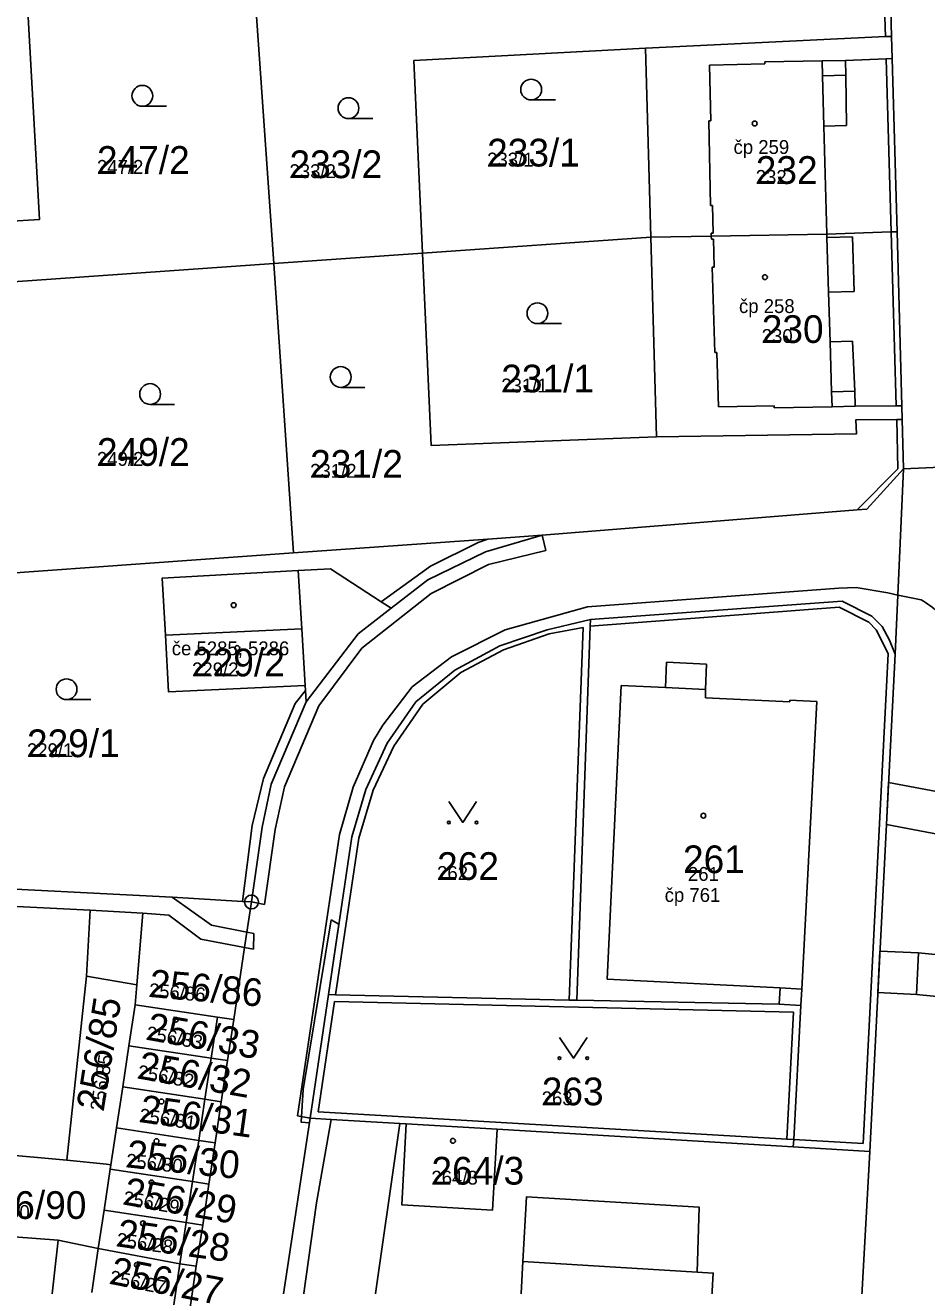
# Model space of a CAD drawing. Extents: x -763628 to -761565, y -976033 to -973833.
# Drawn here: x -762377.8 to -762312.8, y -974602.2 to -974511.2 of the extents above; entities that cross this region are included whole.
import ezdxf

# ---------------------------------------------------------------- set-up
doc = ezdxf.new("R2010")
doc.units = 0
for name, color, linetype in [('KN_cisla parcel 1000', 7, 'Continuous'), ('KN_cisla parcel 500', 7, 'Continuous'), ('KN_cisla popisna 500', 7, 'Continuous'), ('KN_hranice parcel', 7, 'Continuous'), ('KN_vecna bremena', 7, 'Continuous'), ('KN_vnitrni kresba parcel', 7, 'Continuous'), ('KN_znacky bodu BP', 7, 'Continuous'), ('KN_znacky budov', 7, 'Continuous'), ('KN_znacky kultur', 7, 'Continuous')]:
    doc.layers.add(name, color=color, linetype=linetype)

msp = doc.modelspace()

# ---------------------------------------------------------------- linework, layer by layer
at = {"layer": 'KN_hranice parcel'}
for p, q in [((-762315.48, -974505.83), (-762315.31, -974512)), ((-762361.25, -974508.46), (-762359.88, -974528.4)), ((-762333.06, -974512.85), (-762332.67, -974526.49)), ((-762332.67, -974526.49), (-762349.14, -974527.65)), ((-762332.67, -974526.49), (-762332.26, -974540.9)), ((-762349.14, -974527.65), (-762359.88, -974528.4)), ((-762378.68, -974529.71), (-762359.88, -974528.4)), ((-762359.88, -974528.4), (-762358.44, -974549.26)), ((-762314.53, -974539.65), (-762314.44, -974543.2)), ((-762358.44, -974549.26), (-762383.59, -974551.08)), ((-762316.87, -974592.46), (-762315.05, -974556.59)), ((-762373.12, -974575.06), (-762402.53, -974573.6)), ((-762369.33, -974575.27), (-762373.12, -974575.06)), ((-762362.76, -974582.94), (-762361.98, -974577.75)), ((-762355.92, -974581.14), (-762357.24, -974590.06)), ((-762369.88, -974581.87), (-762370.32, -974584.83)), ((-762363.21, -974585.91), (-762362.76, -974582.94)), ((-762370.32, -974584.83), (-762370.77, -974587.8)), ((-762363.66, -974588.87), (-762363.21, -974585.91)), ((-762370.77, -974587.8), (-762371.22, -974590.76)), ((-762364.1, -974591.84), (-762363.66, -974588.87)), ((-762350.32, -974590.47), (-762343.75, -974590.86)), ((-762371.22, -974590.76), (-762371.62, -974593.42)), ((-762343.75, -974590.86), (-762322.39, -974592.13)), ((-762364.55, -974594.81), (-762364.1, -974591.84)), ((-762322.39, -974592.13), (-762316.87, -974592.46)), ((-762382.37, -974592.4), (-762374.81, -974593.08)), ((-762371.67, -974593.73), (-762372.12, -974596.69)), ((-762371.62, -974593.42), (-762371.67, -974593.73)), ((-762365, -974597.77), (-762364.55, -974594.81)), ((-762372.12, -974596.69), (-762372.54, -974599.47)), ((-762365.46, -974600.74), (-762365, -974597.77)), ((-762377.48, -974617.38), (-762375.43, -974598.87)), ((-762372.54, -974599.47), (-762375.43, -974598.87)), ((-762372.54, -974599.47), (-762373.01, -974602.63)), ((-762365.9, -974603.71), (-762365.46, -974600.74))]:
    msp.add_line(p, q, dxfattribs=at)
for points in [[(-762385.82, -974525.76), (-762376.78, -974525.22), (-762377.64, -974509.75)], [(-762315.31, -974512), (-762315.74, -974512.02), (-762333.06, -974512.85)], [(-762314.9, -974526.1), (-762315.26, -974513.59), (-762315.31, -974512)], [(-762333.06, -974512.85), (-762349.76, -974513.75), (-762349.14, -974527.65)], [(-762314.9, -974526.1), (-762315.33, -974526.11), (-762319.97, -974526.27), (-762328.31, -974526.41), (-762332.67, -974526.49)], [(-762314.53, -974539.65), (-762314.56, -974538.66), (-762314.9, -974526.1)], [(-762349.14, -974527.65), (-762348.52, -974541.52), (-762332.26, -974540.9)], [(-762332.26, -974540.9), (-762317.84, -974540.69), (-762317.88, -974539.67), (-762314.93, -974539.65), (-762314.53, -974539.65)], [(-762314.44, -974543.2), (-762317.09, -974546.11), (-762317.78, -974546.17), (-762340.52, -974547.99)], [(-762314.44, -974543.2), (-762314.86, -974552.31), (-762315.05, -974556.59)], [(-762340.52, -974547.99), (-762344.42, -974548.27), (-762358.44, -974549.26)], [(-762351.4, -974553.27), (-762348.76, -974551.22), (-762344.6, -974549.19), (-762340.52, -974547.99)], [(-762357.54, -974560.01), (-762357.59, -974559.2), (-762357.61, -974558.85), (-762367.46, -974559.3), (-762367.69, -974555.2), (-762367.92, -974551.09), (-762358.11, -974550.55), (-762355.78, -974550.42), (-762352.12, -974552.8), (-762351.4, -974553.27)], [(-762315.05, -974556.59), (-762315.46, -974555.58), (-762315.98, -974554.59), (-762316.72, -974553.83), (-762318.87, -974552.75), (-762337.03, -974554.08)], [(-762357.54, -974560.01), (-762353.78, -974555.1), (-762351.4, -974553.27)], [(-762337.03, -974554.08), (-762337.53, -974554.2), (-762340.15, -974554.82), (-762343.57, -974555.97), (-762346.81, -974557.74), (-762349.62, -974560.02), (-762351.7, -974562.99), (-762353.24, -974566.35), (-762354.23, -974569.77), (-762355.92, -974581.14)], [(-762337.03, -974554.08), (-762337.05, -974554.57), (-762338.01, -974581.55)], [(-762361.48, -974574.46), (-762360.72, -974569.05), (-762360.06, -974565.95), (-762357.54, -974560.01)], [(-762383.26, -974573.3), (-762367.2, -974574.11), (-762362.14, -974574.42), (-762361.48, -974574.46)], [(-762374.81, -974593.08), (-762373.39, -974579.82), (-762373.12, -974575.06)], [(-762361.98, -974577.75), (-762361.81, -974576.64), (-762361.48, -974574.46)], [(-762369.88, -974581.87), (-762369.76, -974580.43), (-762369.33, -974575.27)], [(-762361.98, -974577.75), (-762365.13, -974577.14), (-762367.45, -974575.41), (-762369.33, -974575.27)], [(-762355.92, -974581.14), (-762355.41, -974581.15), (-762338.55, -974581.54), (-762338.01, -974581.55)], [(-762362.76, -974582.94), (-762363.94, -974582.76), (-762369.88, -974581.87)], [(-762338.01, -974581.55), (-762323.4, -974581.83), (-762321.84, -974581.92), (-762322.36, -974591.6), (-762322.39, -974592.13)], [(-762363.21, -974585.91), (-762364.39, -974585.73), (-762370.32, -974584.83)], [(-762363.66, -974588.87), (-762364.84, -974588.69), (-762370.77, -974587.8)], [(-762357.24, -974590.06), (-762362.84, -974626.97), (-762363.63, -974631.1), (-762365.36, -974638.07), (-762367.56, -974644.53)], [(-762357.24, -974590.06), (-762355.74, -974590.15), (-762350.77, -974590.44), (-762350.32, -974590.47)], [(-762343.75, -974590.86), (-762344.1, -974596.7), (-762350.64, -974596.31), (-762350.32, -974590.47)], [(-762364.1, -974591.84), (-762365.29, -974591.66), (-762371.22, -974590.76)], [(-762375.43, -974598.87), (-762383.08, -974598.28), (-762382.37, -974592.4)], [(-762374.81, -974593.08), (-762371.94, -974593.39), (-762371.62, -974593.42)], [(-762319.64, -974642.39), (-762319.28, -974635.8), (-762316.87, -974592.46)], [(-762364.55, -974594.81), (-762365.74, -974594.63), (-762371.67, -974593.73)], [(-762324.2, -974627.44), (-762338.71, -974626.51), (-762341.63, -974626.32), (-762342.11, -974634.68), (-762342.19, -974635.75), (-762342.28, -974636.95), (-762346.13, -974636.78), (-762345.95, -974635.59), (-762345.4, -974624.52), (-762351.39, -974623.22), (-762351.21, -974622.61), (-762350.73, -974620.91), (-762345.24, -974622.18), (-762343.05, -974622.69), (-762341.91, -974600.41), (-762341.64, -974595.74), (-762329.18, -974596.49), (-762329.32, -974601.17), (-762328.16, -974601.24), (-762328.39, -974605.06), (-762328.16, -974605.07), (-762328.37, -974608.45), (-762323.2, -974608.77), (-762324.2, -974627.44)], [(-762365, -974597.77), (-762366.19, -974597.59), (-762372.12, -974596.69)], [(-762365.46, -974600.74), (-762366.64, -974600.56), (-762372.54, -974599.47)]]:
    msp.add_lwpolyline(points, dxfattribs=at)
at = {"layer": 'KN_vecna bremena'}
for points in [[(-762315.67, -974568.86), (-762311.86, -974569.58), (-762311.3, -974566.64), (-762315.52, -974565.83)], [(-762355.74, -974575.74), (-762357.74, -974587.99), (-762357.89, -974590.36), (-762357.29, -974590.4), (-762357.24, -974590.06), (-762355.92, -974581.14), (-762355.17, -974576.07)], [(-762316.14, -974578), (-762316.29, -974581), (-762313.5, -974581.13), (-762305.88, -974581.89), (-762305.61, -974578.91), (-762313.36, -974578.13)], [(-762316.29, -974581), (-762313.5, -974581.13), (-762313.36, -974578.13), (-762316.14, -974578)]]:
    msp.add_lwpolyline(points, close=True, dxfattribs=at)
at = {"layer": 'KN_vnitrni kresba parcel'}
for p, q in [((-762315.74, -974512.02), (-762315.92, -974505.86)), ((-762328.44, -974514.07), (-762324.44, -974513.99)), ((-762328.34, -974518.1), (-762328.44, -974514.07)), ((-762324.44, -974513.84), (-762320.31, -974513.76)), ((-762324.44, -974513.99), (-762324.44, -974513.84)), ((-762320.31, -974513.76), (-762318.62, -974513.73)), ((-762320.28, -974514.85), (-762320.31, -974513.76)), ((-762318.62, -974513.73), (-762315.69, -974513.61)), ((-762318.62, -974513.73), (-762318.6, -974514.81)), ((-762315.69, -974513.61), (-762315.26, -974513.59)), ((-762315.33, -974526.11), (-762315.69, -974513.61)), ((-762320.28, -974514.85), (-762318.6, -974514.81)), ((-762320.18, -974518.47), (-762320.28, -974514.85)), ((-762318.6, -974514.81), (-762318.55, -974518.42)), ((-762328.36, -974524.21), (-762328.49, -974518.1)), ((-762328.49, -974518.1), (-762328.34, -974518.1)), ((-762318.55, -974518.42), (-762320.18, -974518.47)), ((-762320.18, -974518.47), (-762319.97, -974526.27)), ((-762328.21, -974524.21), (-762328.36, -974524.21)), ((-762328.16, -974526.21), (-762328.21, -974524.21)), ((-762328.31, -974526.41), (-762328.31, -974526.21)), ((-762328.31, -974526.21), (-762328.16, -974526.21)), ((-762328.3, -974526.63), (-762328.31, -974526.41)), ((-762328.15, -974526.63), (-762328.3, -974526.63)), ((-762328.09, -974528.65), (-762328.15, -974526.63)), ((-762319.97, -974526.27), (-762319.96, -974526.52)), ((-762318.12, -974526.46), (-762319.96, -974526.52)), ((-762319.96, -974526.52), (-762319.84, -974530.46)), ((-762317.99, -974530.4), (-762318.12, -974526.46)), ((-762314.96, -974538.66), (-762315.33, -974526.11)), ((-762328.24, -974528.66), (-762328.09, -974528.65)), ((-762328.06, -974534.81), (-762328.24, -974528.66)), ((-762319.84, -974530.46), (-762317.99, -974530.4)), ((-762319.84, -974530.46), (-762319.74, -974534.05)), ((-762319.74, -974534.05), (-762318.11, -974534)), ((-762319.63, -974537.66), (-762319.74, -974534.05)), ((-762318.11, -974534), (-762317.96, -974537.61)), ((-762327.91, -974534.8), (-762328.06, -974534.81)), ((-762327.79, -974538.73), (-762327.91, -974534.8)), ((-762317.96, -974537.61), (-762319.63, -974537.66)), ((-762319.63, -974537.66), (-762319.59, -974538.73)), ((-762317.96, -974537.61), (-762317.92, -974538.68)), ((-762323.77, -974538.66), (-762327.79, -974538.73)), ((-762323.77, -974538.81), (-762323.77, -974538.66)), ((-762317.92, -974538.68), (-762319.59, -974538.73)), ((-762314.96, -974538.66), (-762317.92, -974538.68)), ((-762314.56, -974538.66), (-762314.96, -974538.66)), ((-762319.59, -974538.73), (-762323.77, -974538.81)), ((-762314.93, -974539.65), (-762314.84, -974543.2)), ((-762317.78, -974546.17), (-762314.84, -974543.2)), ((-762309.47, -974542.99), (-762314.44, -974543.2)), ((-762348.57, -974550.24), (-762345.13, -974548.53)), ((-762345.13, -974548.53), (-762344.42, -974548.27)), ((-762340.25, -974549.09), (-762340.52, -974547.99)), ((-762344.37, -974550.1), (-762340.25, -974549.09)), ((-762352.12, -974552.8), (-762348.57, -974550.24)), ((-762348.52, -974552.21), (-762344.37, -974550.1)), ((-762357.85, -974554.74), (-762358.11, -974550.55)), ((-762353.51, -974556.15), (-762348.52, -974552.21)), ((-762337.25, -974553.17), (-762319.1, -974551.82)), ((-762319.1, -974551.82), (-762317.86, -974551.77)), ((-762317.86, -974551.77), (-762315.58, -974552.16)), ((-762315.58, -974552.16), (-762314.86, -974552.31)), ((-762314.86, -974552.31), (-762313.17, -974552.67)), ((-762343.19, -974554.82), (-762337.25, -974553.17)), ((-762319.09, -974553.19), (-762337.05, -974554.57)), ((-762316.94, -974554.28), (-762319.09, -974553.19)), ((-762367.69, -974555.2), (-762357.85, -974554.74)), ((-762357.61, -974558.85), (-762357.85, -974554.74)), ((-762347.05, -974556.78), (-762343.19, -974554.82)), ((-762340.01, -974555.1), (-762337.55, -974554.66)), ((-762337.55, -974554.66), (-762338.55, -974581.54)), ((-762316.42, -974554.82), (-762316.94, -974554.28)), ((-762315.9, -974555.81), (-762316.42, -974554.82)), ((-762343.31, -974556.27), (-762340.01, -974555.1)), ((-762315.55, -974556.56), (-762315.9, -974555.81)), ((-762356.62, -974560.31), (-762353.51, -974556.15)), ((-762349.89, -974558.93), (-762347.05, -974556.78)), ((-762346.38, -974557.91), (-762343.31, -974556.27)), ((-762317.34, -974591.89), (-762315.55, -974556.56)), ((-762331.62, -974558.99), (-762331.53, -974557.16)), ((-762331.53, -974557.16), (-762328.65, -974557.3)), ((-762328.65, -974557.3), (-762328.73, -974559.13)), ((-762349.13, -974560.18), (-762346.38, -974557.91)), ((-762358.34, -974560.13), (-762357.59, -974559.2)), ((-762352.01, -974561.7), (-762349.89, -974558.93)), ((-762335.82, -974580.02), (-762334.82, -974558.84)), ((-762334.82, -974558.84), (-762331.62, -974558.99)), ((-762328.73, -974559.13), (-762331.62, -974558.99)), ((-762328.73, -974559.13), (-762328.72, -974559.72)), ((-762360.61, -974565.56), (-762358.34, -974560.13)), ((-762359.1, -974566.14), (-762356.62, -974560.31)), ((-762351.21, -974563.21), (-762349.13, -974560.18)), ((-762328.72, -974559.72), (-762322.65, -974560.03)), ((-762322.65, -974560.03), (-762322.65, -974559.89)), ((-762322.65, -974559.89), (-762320.69, -974559.99)), ((-762320.69, -974559.99), (-762321.78, -974580.74)), ((-762352.67, -974562.8), (-762352.01, -974561.7)), ((-762354.15, -974566.17), (-762352.67, -974562.8)), ((-762352.71, -974566.39), (-762351.21, -974563.21)), ((-762361.42, -974568.93), (-762360.61, -974565.56)), ((-762359.78, -974569.23), (-762359.1, -974566.14)), ((-762355.12, -974569.6), (-762354.15, -974566.17)), ((-762353.74, -974569.85), (-762352.71, -974566.39)), ((-762362.14, -974574.42), (-762361.42, -974568.93)), ((-762360.55, -974574.65), (-762359.78, -974569.23)), ((-762358.17, -974589.88), (-762355.12, -974569.6)), ((-762355.41, -974581.15), (-762353.74, -974569.85)), ((-762367.2, -974574.11), (-762364.36, -974576.14)), ((-762361.48, -974574.46), (-762360.55, -974574.65)), ((-762364.36, -974576.14), (-762361.81, -974576.64)), ((-762361.81, -974576.64), (-762361.31, -974576.74)), ((-762361.31, -974576.74), (-762361.33, -974577.87)), ((-762361.33, -974577.87), (-762361.98, -974577.75)), ((-762373.39, -974579.82), (-762369.76, -974580.43)), ((-762323.34, -974580.66), (-762335.82, -974580.02)), ((-762323.4, -974581.83), (-762323.34, -974580.66)), ((-762323.34, -974580.66), (-762321.78, -974580.74)), ((-762321.78, -974580.74), (-762321.84, -974581.92)), ((-762355.48, -974581.63), (-762356.66, -974589.6)), ((-762322.37, -974582.41), (-762355.48, -974581.63)), ((-762363.94, -974582.76), (-762364.39, -974585.73)), ((-762322.86, -974591.57), (-762322.37, -974582.41)), ((-762364.39, -974585.73), (-762364.84, -974588.69)), ((-762364.84, -974588.69), (-762365.29, -974591.66)), ((-762356.66, -974589.6), (-762322.86, -974591.57)), ((-762357.24, -974590.06), (-762358.17, -974589.88)), ((-762355.74, -974590.15), (-762356.78, -974596.18)), ((-762353.83, -974611.61), (-762350.77, -974590.44)), ((-762365.29, -974591.66), (-762365.74, -974594.63)), ((-762322.86, -974591.57), (-762322.36, -974591.6)), ((-762322.36, -974591.6), (-762317.34, -974591.89)), ((-762365.74, -974594.63), (-762366.19, -974597.59)), ((-762356.78, -974596.18), (-762360.24, -974620.63)), ((-762366.19, -974597.59), (-762366.64, -974600.56)), ((-762341.91, -974600.41), (-762329.32, -974601.17)), ((-762366.64, -974600.56), (-762367.08, -974603.53))]:
    msp.add_line(p, q, dxfattribs=at)
msp.add_lwpolyline([(-762313.17, -974552.67), (-762313.004, -974552.761), (-762312.842, -974552.859), (-762312.684, -974552.962), (-762312.531, -974553.072), (-762312.381, -974553.187), (-762312.236, -974553.309), (-762312.096, -974553.435), (-762311.961, -974553.567), (-762311.831, -974553.705), (-762311.706, -974553.847), (-762311.587, -974553.994), (-762311.474, -974554.145), (-762311.367, -974554.301), (-762311.266, -974554.46), (-762311.171, -974554.624), (-762311.082, -974554.791), (-762311, -974554.961), (-762310.925, -974555.134), (-762310.856, -974555.31), (-762310.795, -974555.489), (-762310.74, -974555.67)], dxfattribs=at)
at = {"layer": 'KN_znacky bodu BP'}
for radius in [0.5, 0.0303]:
    msp.add_circle((-762361.48, -974574.46), radius, dxfattribs=at)
at = {"layer": 'KN_znacky budov'}
for centre in [(-762325.177, -974518.289), (-762324.437, -974529.379), (-762362.767, -974553.039), (-762362.507, -974556.139), (-762328.877, -974568.229), (-762366.947, -974582.959), (-762367.507, -974585.829), (-762367.977, -974588.859), (-762368.337, -974591.719), (-762346.947, -974591.699), (-762368.697, -974594.699), (-762369.307, -974597.649), (-762369.747, -974600.649)]:
    msp.add_circle(centre, 0.175, dxfattribs=at)
at = {"layer": 'KN_znacky kultur'}
for p, q in [((-762341.303, -974516.59), (-762339.553, -974516.59)), ((-762369.353, -974517.04), (-762367.603, -974517.04)), ((-762354.483, -974517.93), (-762352.733, -974517.93)), ((-762340.853, -974532.73), (-762339.103, -974532.73)), ((-762355.043, -974537.33), (-762353.293, -974537.33)), ((-762368.793, -974538.56), (-762367.043, -974538.56)), ((-762374.823, -974559.86), (-762373.073, -974559.86))]:
    msp.add_line(p, q, dxfattribs=at)
for points in [[(-762347.24, -974567.219), (-762346.24, -974568.72), (-762345.24, -974567.219)], [(-762339.26, -974584.229), (-762338.26, -974585.73), (-762337.26, -974584.229)]]:
    msp.add_lwpolyline(points, dxfattribs=at)
for centre, radius in [((-762369.353, -974516.29), 0.75), ((-762341.303, -974515.84), 0.75), ((-762354.483, -974517.18), 0.75), ((-762340.853, -974531.98), 0.75), ((-762355.043, -974536.58), 0.75), ((-762368.793, -974537.81), 0.75), ((-762374.823, -974559.11), 0.75), ((-762347.24, -974568.719), 0.1), ((-762345.24, -974568.719), 0.1), ((-762339.26, -974585.729), 0.1), ((-762337.26, -974585.729), 0.1)]:
    msp.add_circle(centre, radius, dxfattribs=at)

# ---------------------------------------------------------------- texts
at = {"layer": 'KN_cisla parcel 1000'}
for s, p in [('233/1', (-762344.48, -974521.39)), ('247/2', (-762372.63, -974521.92)), ('233/2', (-762358.74, -974522.23)), ('232', (-762325.1, -974522.644)), ('230', (-762324.667, -974534.122)), ('231/1', (-762343.46, -974537.69)), ('249/2', (-762372.63, -974542.99)), ('231/2', (-762357.25, -974543.85)), ('229/2', (-762365.767, -974558.178)), ('229/1', (-762377.68, -974564.01)), ('261', (-762330.35, -974572.38)), ('262', (-762348.09, -974572.87)), ('263', (-762340.54, -974589.13)), ('264/3', (-762348.499, -974594.853)), ('256/90', (-762381.57, -974597.33))]:
    msp.add_text(s, height=2, dxfattribs=at).set_placement(p)
for s, rotation, p in [('256/86', 355, (-762368.916, -974581.307)), ('256/85', 81, (-762372.145, -974589.593)), ('256/33', 350, (-762369.133, -974584.388)), ('256/32', 350, (-762369.76, -974587.187)), ('256/31', 352, (-762369.627, -974590.334)), ('256/30', 354, (-762370.574, -974593.601)), ('256/29', 350, (-762370.801, -974596.28)), ('256/28', 352, (-762371.276, -974599.301)), ('256/27', 349, (-762371.78, -974602.004))]:
    msp.add_text(s, height=2, rotation=rotation, dxfattribs=at).set_placement(p)
at = {"layer": 'KN_cisla parcel 500'}
for s, p in [('233/1', (-762344.48, -974521.39)), ('247/2', (-762372.63, -974521.92)), ('233/2', (-762358.74, -974522.23)), ('232', (-762325.1, -974522.644)), ('230', (-762324.667, -974534.122)), ('231/1', (-762343.46, -974537.69)), ('249/2', (-762372.63, -974542.99)), ('231/2', (-762357.25, -974543.85)), ('229/2', (-762365.767, -974558.178)), ('229/1', (-762377.68, -974564.01)), ('262', (-762348.09, -974572.87)), ('261', (-762329.995, -974572.937)), ('263', (-762340.54, -974589.13)), ('264/3', (-762348.499, -974594.853)), ('256/90', (-762381.57, -974597.33))]:
    msp.add_text(s, height=1, dxfattribs=at).set_placement(p)
for s, rotation, p in [('256/86', 355, (-762368.916, -974581.307)), ('256/33', 350, (-762369.133, -974584.388)), ('256/85', 81, (-762372.145, -974589.593)), ('256/32', 350, (-762369.76, -974587.187)), ('256/31', 352, (-762369.627, -974590.334)), ('256/30', 354, (-762370.574, -974593.601)), ('256/29', 350, (-762370.801, -974596.28)), ('256/28', 352, (-762371.276, -974599.301)), ('256/27', 349, (-762371.78, -974602.004))]:
    msp.add_text(s, height=1, rotation=rotation, dxfattribs=at).set_placement(p)
at = {"layer": 'KN_cisla popisna 500'}
for s, p in [('čp 259', (-762326.701, -974520.485)), ('čp 258', (-762326.308, -974531.963)), ('če 5285, 5286', (-762367.232, -974556.66)), ('čp 761', (-762331.67, -974574.455))]:
    msp.add_text(s, height=1, dxfattribs=at).set_placement(p)

doc.saveas('drawing.dxf')
